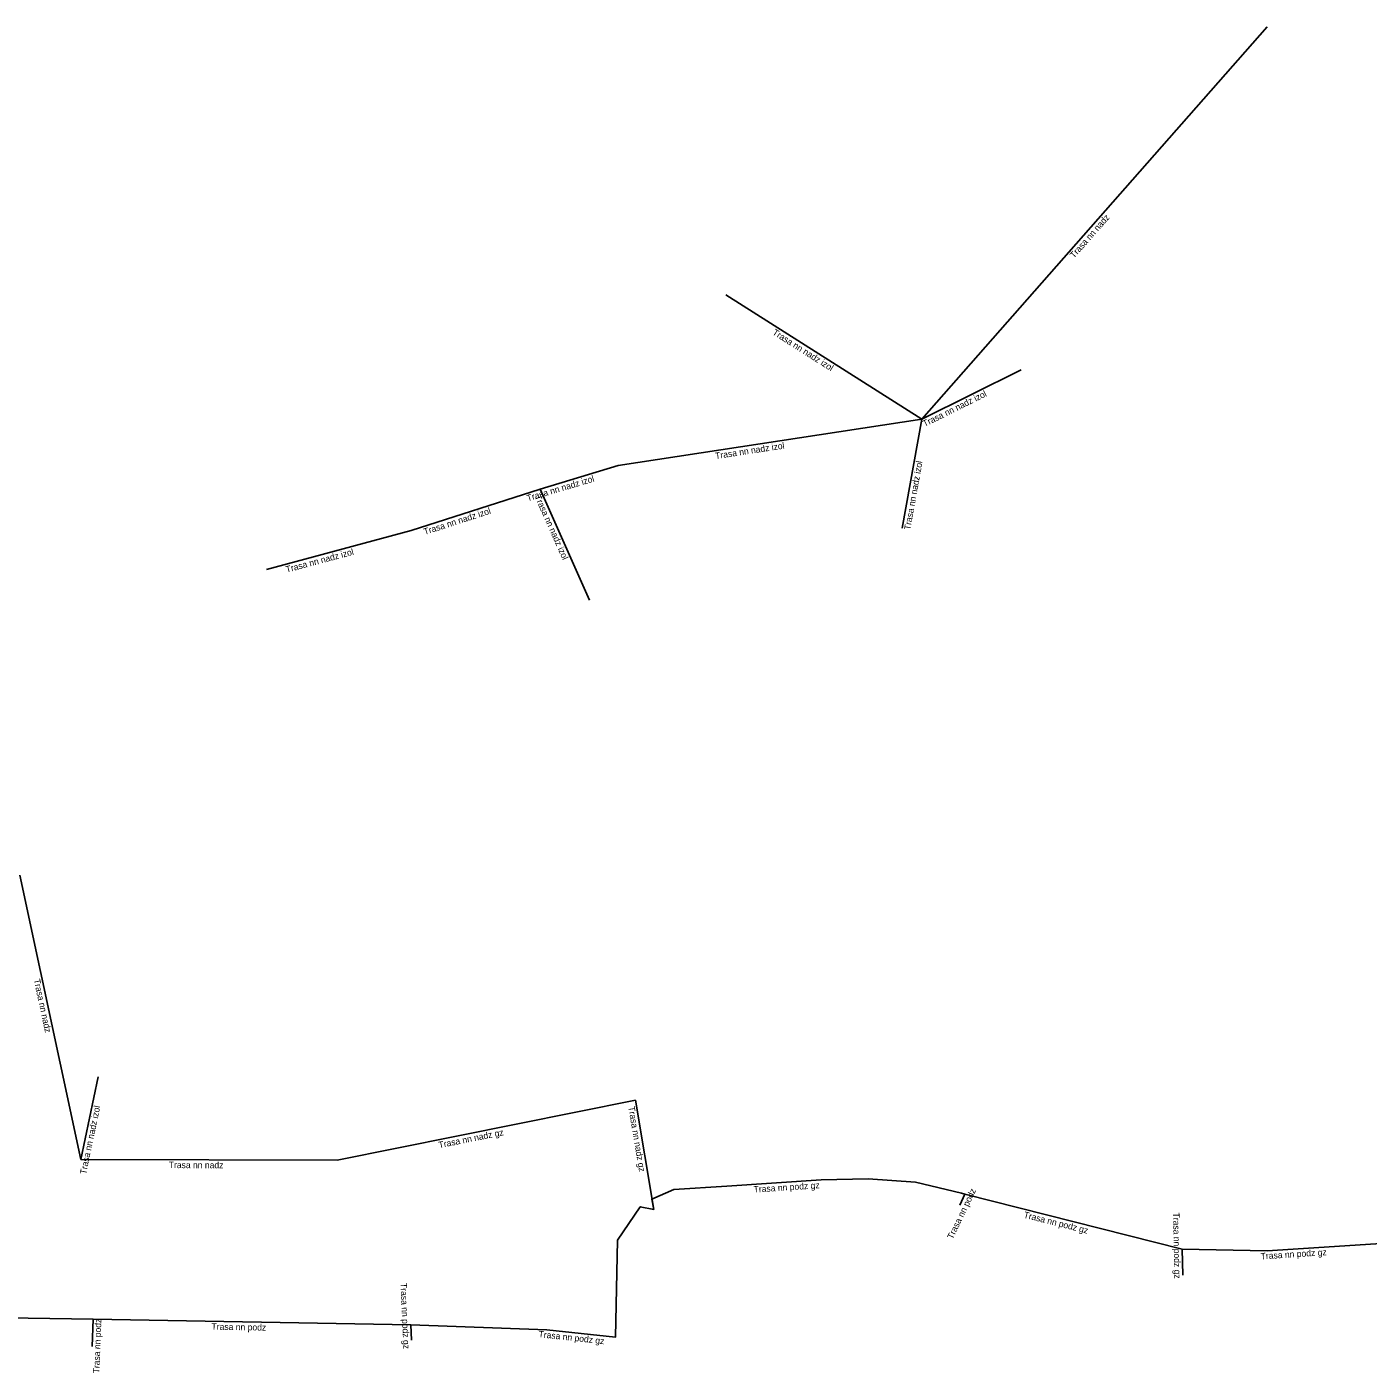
# Model space of a CAD drawing. Extents: x -778104 to -777779, y -1025034 to -1024901.
# Drawn here: x -777998.5 to -777893.7, y -1025005.9 to -1024900.7 of the extents above; entities that cross this region are included whole.
import ezdxf

# ---------------------------------------------------------------- set-up
doc = ezdxf.new("R2010")
doc.units = 0
doc.layers.add('Popiskový text - Ostatní atributy Trasy', color=7, linetype='Continuous')
doc.layers.add('Spojnice NN', color=7, linetype='Continuous')

msp = doc.modelspace()

# ---------------------------------------------------------------- linework, layer by layer
at = {"layer": 'Spojnice NN'}
for points in [[(-777901.61, -1024900.65), (-777928.6, -1024931.31)], [(-777928.6, -1024931.31), (-777943.9, -1024921.6)], [(-777928.6, -1024931.31), (-777920.84, -1024927.46)], [(-777928.6, -1024931.31), (-777952.32, -1024934.94)], [(-777928.6, -1024931.31), (-777930.12, -1024939.82)], [(-777952.32, -1024934.94), (-777958.41, -1024936.77)], [(-777958.41, -1024936.77), (-777968.49, -1024940.02)], [(-777958.41, -1024936.77), (-777954.56, -1024945.46)], [(-777968.49, -1024940.02), (-777979.81, -1024943.07)], [(-777999.08, -1024966.94), (-777994.32, -1024989.16)], [(-777994.32, -1024989.16), (-777992.96, -1024982.7)], [(-777974.27, -1024989.23), (-777950.96, -1024984.52)], [(-777949.53, -1024993.07), (-777950.96, -1024984.52)], [(-777994.32, -1024989.16), (-777974.27, -1024989.23)], [(-777925.22, -1024991.89), (-777925.48, -1024991.8), (-777929.08, -1024990.95), (-777932.79, -1024990.67), (-777936.47, -1024990.76), (-777943.83, -1024991.25), (-777947.96, -1024991.52), (-777949.69, -1024992.28), (-777949.53, -1024993.07)], [(-777925.22, -1024991.89), (-777925.62, -1024992.74)], [(-777908.25, -1024996.17), (-777925.22, -1024991.89)], [(-777949.53, -1024993.07), (-777950.6, -1024992.86), (-777952.38, -1024995.47), (-777952.53, -1025003.06), (-777957.89, -1025002.47), (-777968.53, -1025002.08)], [(-777888.28, -1024995.45), (-777901.6, -1024996.3), (-777908.25, -1024996.17)], [(-777908.25, -1024996.17), (-777908.2, -1024998.22)], [(-777993.35, -1025001.66), (-778030.6, -1025001.07), (-778031.48, -1025001.06)], [(-777993.35, -1025001.66), (-777993.43, -1025003.78)], [(-777993.35, -1025001.66), (-777968.53, -1025002.08)], [(-777968.53, -1025002.08), (-777968.48, -1025003.3)]]:
    msp.add_lwpolyline(points, dxfattribs=at)

# ---------------------------------------------------------------- texts
at = {"layer": 'Popiskový text - Ostatní atributy Trasy'}
for s, rotation, p in [('Trasa nn nadz', 48.6375, (-777916.7, -1024918.77)), ('Trasa nn nadz izol', 327.5911, (-777940.31, -1024924.65)), ('Trasa nn nadz izol', 26.3728, (-777928.37, -1024931.92)), ('Trasa nn nadz izol', 8.6971, (-777944.7, -1024934.43)), ('Trasa nn nadz izol', 79.9014, (-777929.49, -1024940)), ('Trasa nn nadz izol', 16.7131, (-777959.38, -1024937.74)), ('Trasa nn nadz izol', 293.9062, (-777958.86, -1024937.36)), ('Trasa nn nadz izol', 17.8893, (-777967.43, -1024940.36)), ('Trasa nn nadz izol', 15.0669, (-777978.22, -1024943.31)), ('Trasa nn nadz', 282.1081, (-777997.99, -1024975.11)), ('Trasa nn nadz izol', 78.1998, (-777993.9, -1024990.36)), ('Trasa nn nadz gz', 279.4895, (-777951.53, -1024985.06)), ('Trasa nn nadz gz', 11.4351, (-777966.3, -1024988.29)), ('Trasa nn nadz', 359.7856, (-777987.44, -1024989.84)), ('Trasa nn podz gz', 3.8182, (-777941.72, -1024991.76)), ('Trasa nn podz', 64.5353, (-777926.18, -1024995.44)), ('Trasa nn podz gz', 345.8391, (-777920.67, -1024993.71)), ('Trasa nn podz gz', 271.2011, (-777908.96, -1024993.32)), ('Trasa nn podz gz', 3.6684, (-777902.1, -1024996.98)), ('Trasa nn podz gz', 272.5791, (-777969.33, -1024998.83)), ('Trasa nn podz', 87.814, (-777992.86, -1025005.89)), ('Trasa nn podz', 359.028, (-777984.1, -1025002.47)), ('Trasa nn podz gz', 353.7784, (-777958.56, -1025003.05))]:
    msp.add_text(s, height=0.5, rotation=rotation, dxfattribs=at).set_placement(p)

doc.saveas('drawing.dxf')
